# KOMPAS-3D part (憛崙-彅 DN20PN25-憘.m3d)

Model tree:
1. Объединить компоненты:1  (labels: СЕНС-ПФ DN20PN25)
2. Эскиз:1
3. Операция выдавливания:1
     Расстояние 1 = 14
4. Фаска:1
     Угол = 45; Длина 1 = 2; Длина 2 = 2

Referenced files in D:\Савин\!СЕНСОР\3D для заказчика\!Новый перечень\СЕНС-ПФ\DN20\: СЕНС-ПФ DN20PN25.a3d
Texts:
  СЕНС-ПФ DN20PN25-СВ
  ООО НПП Сенсор
  СЕНС-ПФ DN20PN25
